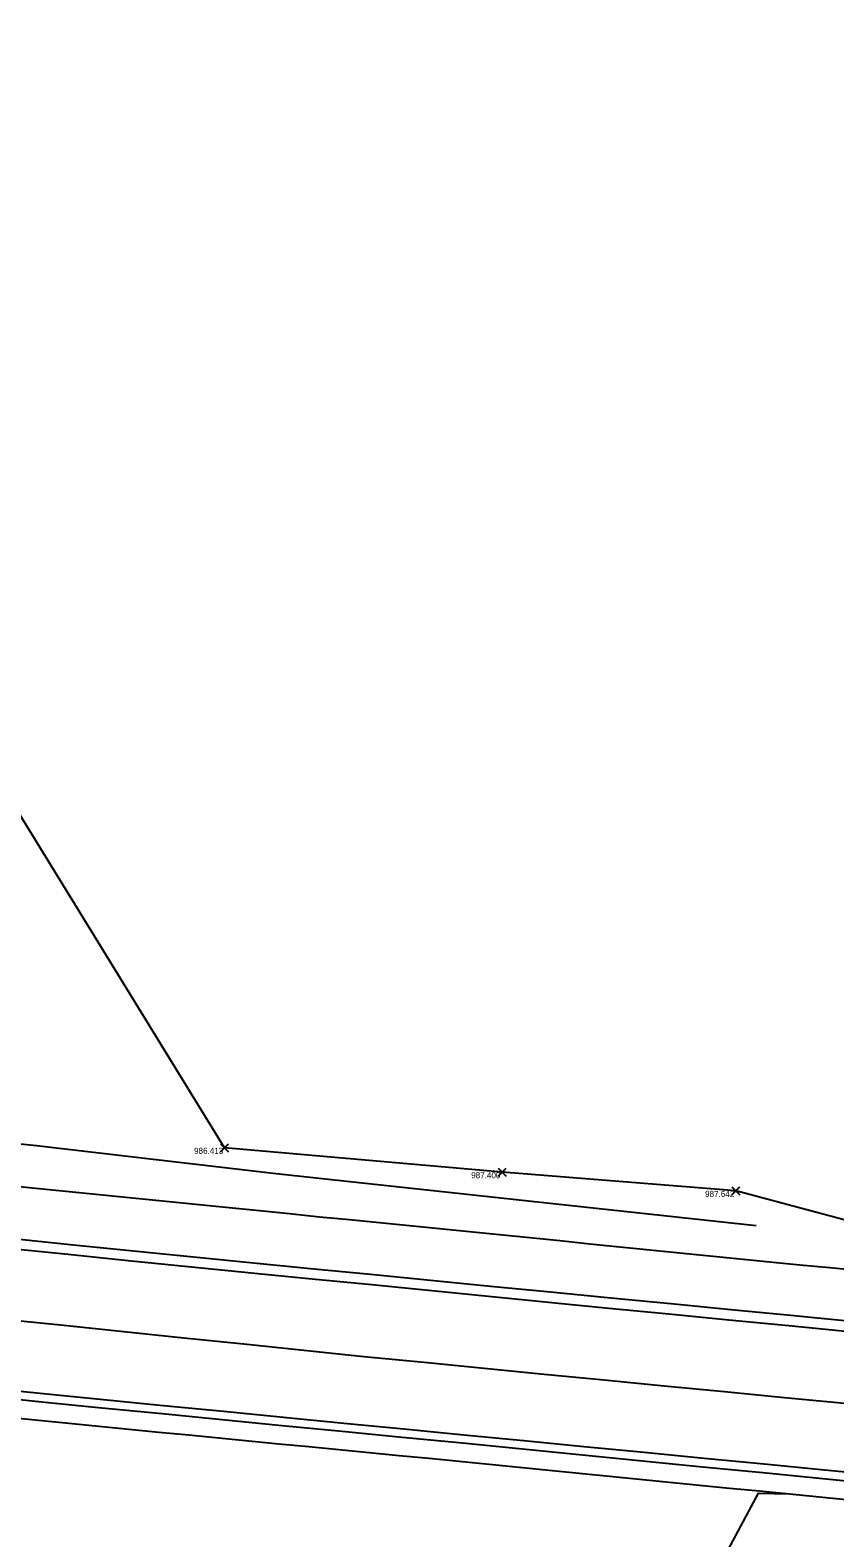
# Model space of a CAD drawing. Extents: x 2065431 to 2068157, y 709104 to 709719.
# Drawn here: x 2067378.4 to 2067511.8, y 709378.9 to 709628.4 of the extents above; entities that cross this region are included whole.
import ezdxf

# ---------------------------------------------------------------- set-up
doc = ezdxf.new("R2010")
doc.units = 0
for name, color, linetype in [('DT_X_Break_Line', 7, 'Continuous'), ('DT_X_Terrain_Boundary', 7, 'Continuous'), ('PM_X_Edge_Line', 7, 'Continuous'), ('PM_X_Lane_Line', 7, 'Continuous'), ('PV_X_EOP', 7, 'Continuous'), ('PV_X_Shoulder_Rumble_Strip', 7, 'Continuous'), ('RW_X_CL_100_Bearings', 7, 'Continuous'), ('SV_X_Text_Name', 7, 'Continuous')]:
    doc.layers.add(name, color=color, linetype=linetype)

msp = doc.modelspace()

# ---------------------------------------------------------------- linework, layer by layer
at = {"layer": 'DT_X_Break_Line'}
msp.add_lwpolyline([(2067498.75, 709430.51), (2067478.87, 709432.67), (2067458.99, 709434.82), (2067439.1, 709436.98), (2067419.22, 709439.13), (2067399.35, 709441.43), (2067379.49, 709443.77), (2067359.59, 709445.77), (2067339.67, 709447.56), (2067319.78, 709449.65), (2067299.9, 709451.81), (2067280.01, 709453.96), (2067260.13, 709456.11), (2067240.26, 709458.41), (2067220.42, 709460.94), (2067200.58, 709463.45), (2067180.69, 709465.52), (2067160.8, 709467.59), (2067140.91, 709469.71), (2067125.91, 709471.33)], dxfattribs=at)
at = {"layer": 'DT_X_Terrain_Boundary'}
for points in [[(2067560.73, 709418.79), (2067495.34, 709436.29), (2067456.65, 709439.38), (2067410.67, 709443.42), (2067361.02, 709524.1), (2067366.41, 709549.95), (2067373.99, 709596.43), (2067354.6, 709616.29), (2067311.55, 709621.56), (2067309.4, 709622.8), (2067308.24, 709625.52), (2067305.17, 709625.78), (2067302.95, 709628.43), (2067239.24, 709621.32), (2067197.78, 709611.01), (2067153.08, 709612.99), (2067144.2, 709539.81), (2067080.32, 709510.92)], [(2067515.45, 709306.5), (2067510.47, 709306.96), (2067505.49, 709307.42), (2067500.51, 709307.88), (2067495.53, 709308.34), (2067490.55, 709308.8), (2067471.85, 709335.31), (2067499.1, 709386.26), (2067504.26, 709386.13), (2067509.24, 709385.64), (2067514.22, 709385.16)]]:
    msp.add_lwpolyline(points, dxfattribs=at)
at = {"layer": 'PM_X_Edge_Line'}
for points in [[(2067374.8, 709426.8), (2067384.74, 709425.8), (2067394.69, 709424.79), (2067404.64, 709423.79), (2067414.59, 709422.8), (2067424.55, 709421.81), (2067434.5, 709420.83), (2067444.45, 709419.85), (2067454.4, 709418.87), (2067464.35, 709417.88), (2067474.3, 709416.9), (2067484.26, 709415.92), (2067494.21, 709414.95), (2067504.16, 709413.98), (2067514.11, 709413.02)], [(2067370.69, 709403.76), (2067380.64, 709402.76), (2067390.59, 709401.77), (2067400.55, 709400.78), (2067410.5, 709399.8), (2067420.45, 709398.82), (2067430.4, 709397.84), (2067440.36, 709396.88), (2067450.31, 709395.91), (2067460.26, 709394.94), (2067470.21, 709393.97), (2067480.17, 709393.01), (2067490.12, 709392.04), (2067500.07, 709391.08), (2067510.03, 709390.12), (2067519.98, 709389.17)]]:
    msp.add_lwpolyline(points, dxfattribs=at)
at = {"layer": 'PM_X_Lane_Line'}
msp.add_lwpolyline([(2067374.07, 709415.07), (2067384.02, 709414.04), (2067393.97, 709413.01), (2067403.91, 709411.98), (2067413.86, 709410.95), (2067423.81, 709409.93), (2067433.76, 709408.9), (2067443.71, 709407.91), (2067453.66, 709406.93), (2067463.61, 709405.96), (2067473.56, 709404.99), (2067483.52, 709404.02), (2067493.47, 709403.06), (2067503.43, 709402.1), (2067513.38, 709401.15)], dxfattribs=at)
at = {"layer": 'PV_X_EOP'}
for points in [[(2067376.63, 709437.04), (2067381.61, 709436.53), (2067386.58, 709436.03), (2067391.56, 709435.52), (2067396.53, 709435.02), (2067401.5, 709434.52), (2067406.48, 709434.02), (2067411.45, 709433.52), (2067416.43, 709433.02), (2067421.4, 709432.52), (2067426.38, 709432.02), (2067431.36, 709431.53), (2067436.33, 709431.03), (2067441.31, 709430.54), (2067446.28, 709430.05), (2067451.26, 709429.56), (2067456.23, 709429.06), (2067461.21, 709428.55), (2067466.18, 709428.05), (2067471.16, 709427.54), (2067476.13, 709427.04), (2067481.11, 709426.54), (2067486.08, 709426.05), (2067491.06, 709425.55), (2067496.03, 709425.06), (2067501.01, 709424.56), (2067505.98, 709424.07), (2067510.96, 709423.58), (2067515.94, 709423.1)], [(2067374.89, 709398.84), (2067379.86, 709398.34), (2067384.84, 709397.85), (2067389.81, 709397.35), (2067394.79, 709396.86), (2067399.76, 709396.37), (2067404.74, 709395.88), (2067409.72, 709395.4), (2067414.69, 709394.91), (2067419.67, 709394.43), (2067424.65, 709393.95), (2067429.62, 709393.47), (2067434.6, 709392.99), (2067439.58, 709392.51), (2067444.55, 709392.04), (2067449.53, 709391.56), (2067454.51, 709391.06), (2067459.48, 709390.56), (2067464.46, 709390.06), (2067469.43, 709389.57), (2067474.41, 709389.07), (2067479.38, 709388.58), (2067484.36, 709388.08), (2067489.33, 709387.59), (2067494.31, 709387.1), (2067499.29, 709386.61), (2067504.26, 709386.13), (2067509.24, 709385.64), (2067514.22, 709385.16)]]:
    msp.add_lwpolyline(points, dxfattribs=at)
at = {"layer": 'PV_X_Shoulder_Rumble_Strip'}
for points in [[(2067375.13, 709428.44), (2067385.07, 709427.44), (2067395.02, 709426.44), (2067404.97, 709425.44), (2067414.93, 709424.45), (2067424.88, 709423.46), (2067434.83, 709422.48), (2067444.78, 709421.5), (2067454.73, 709420.52), (2067464.68, 709419.55), (2067474.64, 709418.58), (2067484.59, 709417.62), (2067494.54, 709416.65), (2067504.5, 709415.7), (2067514.45, 709414.74)], [(2067370.44, 709402.39), (2067380.39, 709401.39), (2067390.34, 709400.4), (2067400.3, 709399.41), (2067410.25, 709398.43), (2067420.2, 709397.46), (2067430.15, 709396.49), (2067440.11, 709395.52), (2067450.06, 709394.56), (2067460.01, 709393.57), (2067469.96, 709392.58), (2067479.91, 709391.6), (2067489.87, 709390.62), (2067499.82, 709389.65), (2067509.77, 709388.68), (2067519.72, 709387.71)]]:
    msp.add_lwpolyline(points, dxfattribs=at)
at = {"layer": 'RW_X_CL_100_Bearings'}
for p, q in [((2067410, 709442.75), (2067411.34, 709444.08)), ((2067410, 709444.08), (2067411.34, 709442.75)), ((2067455.98, 709438.71), (2067457.31, 709440.05)), ((2067455.98, 709440.05), (2067457.31, 709438.71)), ((2067494.68, 709435.62), (2067496.01, 709436.95)), ((2067494.68, 709436.95), (2067496.01, 709435.62))]:
    msp.add_line(p, q, dxfattribs=at)

# ---------------------------------------------------------------- texts
at = {"layer": 'SV_X_Text_Name'}
for s, p in [('986.413', (2067405.61, 709442.42)), ('987.400', (2067451.53, 709438.38)), ('987.642', (2067490.27, 709435.29))]:
    msp.add_text(s, height=1, dxfattribs=at).set_placement(p)

doc.saveas('drawing.dxf')
